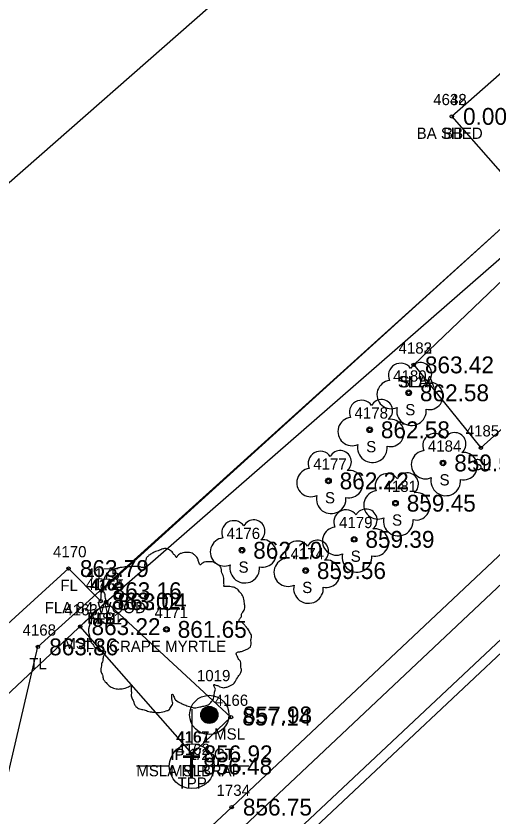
# Model space of a CAD drawing. Extents: x 1622501 to 1626664, y 1117816 to 1121579.
# Drawn here: x 1625061.6 to 1625103.9, y 1120306.8 to 1120378.1 of the extents above; entities that cross this region are included whole.
import ezdxf

# ---------------------------------------------------------------- set-up
doc = ezdxf.new("R2010")
doc.units = 0
for name, color, linetype in [('RD_EX_Bldg', 7, 'Continuous'), ('RD_EX_Bldg_txCode', 7, 'Continuous'), ('RD_EX_Conc', 7, 'Continuous'), ('RD_EX_Conc_txCode', 7, 'Continuous'), ('RD_EX_DR_Pipe', 7, 'Continuous'), ('RD_EX_DV_Prop_txCode', 7, 'Continuous'), ('RD_EX_DV_PropPin', 7, 'Continuous'), ('RD_EX_Fence_Other', 7, 'Continuous'), ('RD_EX_Fence_Other_txCode', 7, 'Continuous'), ('RD_EX_Misc', 7, 'Continuous'), ('RD_EX_Misc_txCode', 7, 'Continuous'), ('RD_EX_Road', 7, 'Continuous'), ('RD_EX_TX_Bldg_ELEV', 7, 'Continuous'), ('RD_EX_TX_Conc_ELEV', 7, 'Continuous'), ('RD_EX_TX_DV_Prop_ELEV', 7, 'Continuous'), ('RD_EX_TX_Fence_Other_ELEV', 7, 'Continuous'), ('RD_EX_TX_Misc_ELEV', 7, 'Continuous'), ('RD_EX_TX_UT_ELEV', 7, 'Continuous'), ('RD_EX_TX_VEG_ELEV', 7, 'Continuous'), ('RD_EX_UT', 7, 'Continuous'), ('RD_EX_UT_txCode', 7, 'Continuous'), ('RD_EX_VEG', 7, 'Continuous'), ('RD_EX_VEG_txCode', 7, 'Continuous'), ('RD_SMD_Locator', 7, 'Continuous')]:
    doc.layers.add(name, color=color, linetype=linetype)

msp = doc.modelspace()

# ---------------------------------------------------------------- linework, layer by layer
at = {"layer": 'RD_EX_Bldg'}
for points in [[(1625050.988, 1120354.576), (1625088.55, 1120387.585), (1625056.123, 1120424.486), (1625018.56, 1120391.478), (1625050.988, 1120354.576)], [(1625100.292, 1120369.177), (1625105.901, 1120362.791), (1625115.068, 1120370.843), (1625109.458, 1120377.229), (1625100.292, 1120369.177)]]:
    msp.add_lwpolyline(points, dxfattribs=at)
at = {"layer": 'RD_EX_Conc'}
for points in [[(1624897.378, 1120127.586), (1624903.697, 1120133.247), (1624939.766, 1120167.411), (1624977.137, 1120202.764), (1625013.589, 1120237.139), (1625049.488, 1120270.838), (1625084.275, 1120303.479), (1625121.787, 1120338.741), (1625157.607, 1120372.541), (1625193.027, 1120405.896), (1625230.27, 1120441.109), (1625263.987, 1120473.049), (1625301.798, 1120509.249), (1625336.15, 1120542.221), (1625372.25, 1120576.993), (1625405.365, 1120609.311), (1625409.32, 1120614.519), (1625412.456, 1120620.32), (1625414.419, 1120627.016), (1625414.966, 1120636.138), (1625412.914, 1120644.37), (1625411.037, 1120648.086), (1625399.274, 1120667.189)], [(1624899.89, 1120137.526), (1624936.243, 1120171.696), (1624973.261, 1120206.726), (1625009.729, 1120241.184), (1625045.817, 1120275.099), (1625080.725, 1120307.719), (1625118.033, 1120342.848), (1625154.459, 1120377.147), (1625189.451, 1120410.103), (1625226.397, 1120445.046), (1625260.082, 1120477.093), (1625298.209, 1120513.612), (1625332.486, 1120546.411), (1625368.395, 1120580.995), (1625401.296, 1120613.087), (1625404.616, 1120617.809), (1625407.287, 1120622.414), (1625408.963, 1120627.094), (1625409.263, 1120635.885), (1625414.414, 1120636.083)]]:
    msp.add_lwpolyline(points, dxfattribs=at)
at = {"layer": 'RD_EX_DR_Pipe'}
msp.add_lwpolyline([(1625495.159, 1120700.169), (1625478.481, 1120693.944), (1625478.481, 1120693.944), (1625401.274, 1120618.609), (1625386.855, 1120595.889), (1625386.855, 1120595.889), (1625239.336, 1120454.576), (1625067.489, 1120292.506), (1624913.323, 1120147.082), (1624906.318, 1120142.577), (1624803.571, 1120043.734), (1624612.212, 1119870.34), (1624528.295, 1119793.118)], dxfattribs=at)
at = {"layer": 'RD_EX_DV_PropPin'}
for p, q in [((1625078.001, 1120315.724), (1625078.001, 1120316.116)), ((1625078.036, 1120315.622), (1625078.036, 1120316.218)), ((1625078.072, 1120315.55), (1625078.072, 1120316.289)), ((1625078.107, 1120315.493), (1625078.107, 1120316.346)), ((1625078.142, 1120315.446), (1625078.142, 1120316.394)), ((1625078.177, 1120315.405), (1625078.177, 1120316.435)), ((1625078.212, 1120315.369), (1625078.212, 1120316.47)), ((1625078.247, 1120315.338), (1625078.247, 1120316.502)), ((1625078.282, 1120315.31), (1625078.282, 1120316.53)), ((1625078.317, 1120315.285), (1625078.317, 1120316.554)), ((1625078.352, 1120315.263), (1625078.352, 1120316.576)), ((1625078.387, 1120315.244), (1625078.387, 1120316.595)), ((1625078.422, 1120315.227), (1625078.422, 1120316.612)), ((1625078.457, 1120315.212), (1625078.457, 1120316.627)), ((1625078.492, 1120315.199), (1625078.492, 1120316.64)), ((1625078.527, 1120315.188), (1625078.527, 1120316.651)), ((1625078.562, 1120315.179), (1625078.562, 1120316.66)), ((1625078.597, 1120315.172), (1625078.597, 1120316.668)), ((1625078.632, 1120315.166), (1625078.632, 1120316.673)), ((1625078.667, 1120315.162), (1625078.667, 1120316.677)), ((1625078.702, 1120315.159), (1625078.702, 1120316.68)), ((1625078.737, 1120315.159), (1625078.737, 1120316.681)), ((1625078.772, 1120315.159), (1625078.772, 1120316.68)), ((1625078.807, 1120315.162), (1625078.807, 1120316.677)), ((1625078.842, 1120315.166), (1625078.842, 1120316.673)), ((1625078.877, 1120315.172), (1625078.877, 1120316.668)), ((1625078.912, 1120315.179), (1625078.912, 1120316.66)), ((1625078.947, 1120315.188), (1625078.947, 1120316.651)), ((1625078.982, 1120315.199), (1625078.982, 1120316.64)), ((1625079.017, 1120315.212), (1625079.017, 1120316.627)), ((1625079.052, 1120315.227), (1625079.052, 1120316.612)), ((1625079.087, 1120315.244), (1625079.087, 1120316.595)), ((1625079.122, 1120315.263), (1625079.122, 1120316.576)), ((1625079.157, 1120315.285), (1625079.157, 1120316.554)), ((1625079.192, 1120315.31), (1625079.192, 1120316.53)), ((1625079.227, 1120315.338), (1625079.227, 1120316.502)), ((1625079.262, 1120315.369), (1625079.262, 1120316.47)), ((1625079.297, 1120315.405), (1625079.297, 1120316.435)), ((1625079.332, 1120315.446), (1625079.332, 1120316.394)), ((1625079.367, 1120315.493), (1625079.367, 1120316.346)), ((1625079.402, 1120315.55), (1625079.402, 1120316.289)), ((1625079.437, 1120315.622), (1625079.437, 1120316.218)), ((1625079.472, 1120315.724), (1625079.472, 1120316.116))]:
    msp.add_line(p, q, dxfattribs=at)
for radius in [1.75, 0.761]:
    msp.add_circle((1625078.737, 1120315.92), radius, dxfattribs=at)
at = {"layer": 'RD_EX_Fence_Other'}
for points in [[(1624882.108, 1120146.413), (1624922.827, 1120188.172), (1624952.576, 1120216.9), (1624993.862, 1120256.562), (1625030.931, 1120289.642), (1625069.578, 1120325.996), (1625106.791, 1120358.455), (1625145.388, 1120394.48), (1625163.872, 1120411.002), (1625180.046, 1120426.703), (1625211.372, 1120456.62), (1625250.442, 1120494.547), (1625284.568, 1120527.631), (1625318.686, 1120557.977), (1625317.764, 1120559.821), (1625354.436, 1120595.487), (1625389.434, 1120629.691)], [(1624968.412, 1120251.923), (1624973.485, 1120246.613), (1625017.999, 1120286.663), (1625019.131, 1120285.989), (1625066.231, 1120328.946), (1625069.089, 1120326.051), (1625069.144, 1120326.972), (1625105.343, 1120359.801), (1625118.176, 1120370.27), (1625118.176, 1120370.27), (1625145.005, 1120394.595), (1625165.443, 1120413.584)]]:
    msp.add_lwpolyline(points, dxfattribs=at)
at = {"layer": 'RD_EX_Misc'}
msp.add_lwpolyline([(1625077.226, 1120312.461), (1625067.266, 1120323.778), (1625069.578, 1120325.996), (1625080.664, 1120315.729), (1625077.226, 1120312.461)], dxfattribs=at)
at = {"layer": 'RD_EX_Road'}
msp.add_lwpolyline([(1624781.367, 1120199.017), (1624784.165, 1120188.994), (1624788.317, 1120183.838), (1624819.769, 1120157.812), (1624850.784, 1120132.057), (1624863.119, 1120123.17), (1624872.562, 1120120.776), (1624881.482, 1120120.158), (1624884.455, 1120120.692), (1624898.026, 1120126.784), (1624903.404, 1120131.449), (1624903.183, 1120131.678), (1624904.185, 1120132.725), (1624940.396, 1120166.874), (1624977.651, 1120202.124), (1625014.07, 1120236.514), (1625050.075, 1120270.322), (1625084.777, 1120302.734), (1625122.295, 1120338.035), (1625158.189, 1120371.975), (1625193.609, 1120405.268), (1625230.886, 1120440.454)], dxfattribs=at)
at = {"layer": 'RD_EX_UT'}
for p, q in [((1625077.183, 1120316.433), (1625077.183, 1120313.363)), ((1625072.252, 1120311.378), (1625075.183, 1120311.378)), ((1625079.183, 1120311.378), (1625082.252, 1120311.378))]:
    msp.add_line(p, q, dxfattribs=at)
msp.add_circle((1625077.183, 1120311.363), 2, dxfattribs=at)
at = {"layer": 'RD_EX_VEG'}
for points in [[(1624992.75, 1120261.436), (1624994.015, 1120256.481), (1625045.588, 1120300.866), (1625059.123, 1120303.266), (1625063.507, 1120321.975), (1625105.343, 1120359.801), (1625167.773, 1120414.629), (1625284.568, 1120527.631), (1625296.639, 1120540.301), (1625291.874, 1120545.154)], [(1625096.903, 1120347.066), (1625102.874, 1120339.698), (1625152.178, 1120384.03), (1625170.927, 1120401.075), (1625165.695, 1120409.022)], [(1625096.903, 1120347.066), (1625107.552, 1120357.235), (1625146.826, 1120391.831), (1625165.695, 1120409.022)]]:
    msp.add_lwpolyline(points, dxfattribs=at)
for centre, radius in [((1625096.462, 1120344.583), 0.25), ((1625092.988, 1120341.291), 0.25), ((1625099.509, 1120338.341), 0.25), ((1625089.325, 1120336.746), 0.25), ((1625095.287, 1120334.761), 0.25), ((1625091.614, 1120331.544), 0.25), ((1625081.644, 1120330.575), 0.25), ((1625087.303, 1120328.766), 0.25), ((1625074.93, 1120323.532), 0.25), ((1625074.918, 1120323.513), 0.0001)]:
    msp.add_circle(centre, radius, dxfattribs=at)
for centre, radius, start, end in [((1625095.741, 1120346.131), 1.084, 34.97629, 204.75602), ((1625097.507, 1120346.285), 0.995, 308.76261, 152.04674), ((1625094.898, 1120344.428), 1.257, 96.45179, 294.73401), ((1625098.301, 1120344.304), 1.218, 256.56668, 98.10463), ((1625092.267, 1120342.838), 1.084, 34.97629, 204.75602), ((1625094.033, 1120342.993), 0.995, 308.76261, 152.04674), ((1625096.707, 1120342.987), 1.318, 166.88266, 5.75893), ((1625091.424, 1120341.135), 1.257, 96.45179, 294.73401), ((1625094.828, 1120341.011), 1.218, 256.56668, 98.10463), ((1625098.788, 1120339.888), 1.084, 34.97629, 204.75602), ((1625100.554, 1120340.043), 0.995, 308.76261, 152.04674), ((1625093.234, 1120339.694), 1.318, 166.88266, 5.75893), ((1625088.604, 1120338.293), 1.084, 34.97629, 204.75602), ((1625090.37, 1120338.448), 0.995, 308.76261, 152.04674), ((1625097.945, 1120338.186), 1.257, 96.45179, 294.73401), ((1625101.349, 1120338.062), 1.218, 256.56668, 98.10463), ((1625087.761, 1120336.59), 1.257, 96.45179, 294.73401), ((1625091.164, 1120336.466), 1.218, 256.56668, 98.10463), ((1625094.566, 1120336.308), 1.084, 34.97629, 204.75602), ((1625096.332, 1120336.463), 0.995, 308.76261, 152.04674), ((1625099.754, 1120336.745), 1.318, 166.88266, 5.75893), ((1625089.57, 1120335.149), 1.318, 166.88266, 5.75893), ((1625093.723, 1120334.605), 1.257, 96.45179, 294.73401), ((1625097.126, 1120334.481), 1.218, 256.56668, 98.10463), ((1625090.893, 1120333.091), 1.084, 34.97629, 204.75602), ((1625092.659, 1120333.246), 0.995, 308.76261, 152.04674), ((1625080.923, 1120332.122), 1.084, 34.97629, 204.75602), ((1625082.689, 1120332.277), 0.995, 308.76261, 152.04674), ((1625095.532, 1120333.164), 1.318, 166.88266, 5.75893), ((1625090.05, 1120331.388), 1.257, 96.45179, 294.73401), ((1625093.454, 1120331.264), 1.218, 256.56668, 98.10463), ((1625080.08, 1120330.419), 1.257, 96.45179, 294.73401), ((1625083.483, 1120330.295), 1.218, 256.56668, 98.10463), ((1625086.582, 1120330.313), 1.084, 34.97629, 204.75602), ((1625088.348, 1120330.468), 0.995, 308.76261, 152.04674), ((1625091.859, 1120329.947), 1.318, 166.88266, 5.75893), ((1625085.739, 1120328.61), 1.257, 96.45179, 294.73401), ((1625089.143, 1120328.486), 1.218, 256.56668, 98.10463), ((1625081.889, 1120328.978), 1.318, 166.88266, 5.75893), ((1625087.549, 1120327.169), 1.318, 166.88266, 5.75893)]:
    msp.add_arc(centre, radius, start, end, dxfattribs=at)
for points in [[(1625075.062, 1120330.699), (1625074.762, 1120330.724), (1625074.438, 1120330.624), (1625074.188, 1120330.524), (1625073.963, 1120330.449), (1625073.738, 1120330.349), (1625073.438, 1120330.174), (1625073.213, 1120329.974), (1625073.088, 1120329.724), (1625073.038, 1120329.499), (1625072.988, 1120329.225), (1625072.988, 1120329.05), (1625072.863, 1120329.025), (1625072.713, 1120329.05), (1625072.463, 1120329.125), (1625072.214, 1120329.125), (1625071.964, 1120329.125), (1625071.614, 1120329.1), (1625071.264, 1120329.1), (1625070.989, 1120329.05), (1625070.664, 1120329), (1625070.289, 1120328.875), (1625069.94, 1120328.75), (1625069.64, 1120328.5), (1625069.39, 1120328.025), (1625069.265, 1120327.675), (1625069.115, 1120327.425), (1625069.265, 1120326.976), (1625069.44, 1120326.626), (1625069.465, 1120326.426), (1625069.54, 1120326.001), (1625069.64, 1120325.776), (1625069.765, 1120325.576), (1625069.69, 1120325.551), (1625069.315, 1120325.501), (1625069.015, 1120325.401), (1625068.59, 1120325.176), (1625068.365, 1120324.951), (1625068.265, 1120324.626), (1625068.24, 1120324.277), (1625068.14, 1120324.077), (1625068.065, 1120323.802), (1625068.04, 1120323.727), (1625067.99, 1120323.402), (1625068.09, 1120322.952), (1625068.115, 1120322.602), (1625068.24, 1120322.377), (1625068.39, 1120322.203), (1625068.565, 1120321.953), (1625068.965, 1120321.728), (1625069.29, 1120321.628), (1625069.49, 1120321.603), (1625069.315, 1120321.103), (1625069.265, 1120320.753), (1625069.14, 1120320.353), (1625069.14, 1120320.278), (1625069.09, 1120319.804), (1625069.24, 1120319.479), (1625069.315, 1120319.104), (1625069.49, 1120318.879), (1625069.765, 1120318.579), (1625070.089, 1120318.354), (1625070.589, 1120318.229), (1625070.989, 1120318.254), (1625071.564, 1120318.429), (1625071.814, 1120318.504), (1625071.789, 1120318.329), (1625071.814, 1120317.954), (1625071.814, 1120317.53), (1625071.964, 1120317.205), (1625072.064, 1120316.93), (1625072.214, 1120316.68), (1625072.538, 1120316.455), (1625072.938, 1120316.38), (1625073.363, 1120316.23), (1625073.813, 1120316.155), (1625074.313, 1120316.13), (1625074.912, 1120316.28), (1625075.187, 1120316.405), (1625075.287, 1120316.58), (1625075.487, 1120316.955), (1625075.437, 1120317.18), (1625075.462, 1120317.78), (1625075.562, 1120317.605), (1625075.737, 1120317.255), (1625076.237, 1120316.955), (1625076.637, 1120316.78), (1625077.111, 1120316.63), (1625077.411, 1120316.555), (1625077.886, 1120316.63), (1625078.261, 1120316.705), (1625078.636, 1120316.83), (1625078.936, 1120317.105), (1625079.111, 1120317.38), (1625079.161, 1120317.655), (1625079.235, 1120318.029), (1625079.285, 1120318.204)], [(1625079.285, 1120318.204), (1625079.211, 1120318.379), (1625079.161, 1120318.629), (1625079.235, 1120318.604), (1625079.41, 1120318.554), (1625079.685, 1120318.429), (1625079.91, 1120318.354), (1625080.235, 1120318.379), (1625080.51, 1120318.479), (1625080.96, 1120318.754), (1625081.235, 1120319.229), (1625081.509, 1120319.629), (1625081.584, 1120319.954), (1625081.534, 1120320.178), (1625081.509, 1120320.678), (1625081.31, 1120320.928), (1625081.26, 1120321.053), (1625081.16, 1120321.453), (1625081.235, 1120321.503), (1625081.509, 1120321.553), (1625081.884, 1120321.678), (1625082.159, 1120321.803), (1625082.384, 1120321.978), (1625082.459, 1120322.203), (1625082.434, 1120322.602), (1625082.484, 1120323.002), (1625082.409, 1120323.152), (1625082.309, 1120323.302), (1625082.234, 1120323.502), (1625082.084, 1120323.652), (1625081.984, 1120323.802), (1625081.884, 1120323.902), (1625081.759, 1120324.052), (1625081.584, 1120324.177), (1625081.435, 1120324.227), (1625081.385, 1120324.377), (1625081.534, 1120324.577), (1625081.584, 1120324.676), (1625081.609, 1120324.901), (1625081.834, 1120325.251), (1625081.884, 1120325.651), (1625081.834, 1120326.076), (1625081.784, 1120326.351), (1625081.634, 1120326.626), (1625081.435, 1120326.876), (1625081.31, 1120327.05), (1625081.135, 1120327.175), (1625080.81, 1120327.3), (1625080.56, 1120327.35), (1625080.21, 1120327.35), (1625080.01, 1120327.4), (1625080.035, 1120327.45), (1625080.035, 1120327.6), (1625080.035, 1120327.875), (1625079.96, 1120328.325), (1625079.81, 1120328.825), (1625079.81, 1120328.85), (1625079.71, 1120329.1), (1625079.485, 1120329.299), (1625079.31, 1120329.399), (1625079.111, 1120329.524), (1625078.861, 1120329.549), (1625078.561, 1120329.549), (1625078.286, 1120329.499), (1625078.086, 1120329.399), (1625077.911, 1120329.274), (1625077.836, 1120329.424), (1625077.736, 1120329.724), (1625077.686, 1120329.874), (1625077.536, 1120330.049), (1625077.311, 1120330.249), (1625076.861, 1120330.374), (1625076.237, 1120330.299), (1625075.937, 1120330.099), (1625075.787, 1120329.924), (1625075.737, 1120330.049), (1625075.537, 1120330.249), (1625075.437, 1120330.424), (1625075.262, 1120330.549), (1625075.112, 1120330.649), (1625075.012, 1120330.699)]]:
    msp.add_spline(points, degree=3, dxfattribs=at)
at = {"layer": 'RD_SMD_Locator'}
for centre in [(1625100.292, 1120369.177), (1625100.292, 1120369.177), (1625096.903, 1120347.066), (1625096.903, 1120347.066), (1625096.462, 1120344.583), (1625092.988, 1120341.291), (1625102.874, 1120339.698), (1625099.509, 1120338.341), (1625089.325, 1120336.746), (1625095.287, 1120334.761), (1625091.614, 1120331.544), (1625081.644, 1120330.575), (1625066.231, 1120328.946), (1625087.303, 1120328.766), (1625069.144, 1120326.972), (1625069.089, 1120326.051), (1625069.578, 1120325.996), (1625069.578, 1120325.996), (1625067.266, 1120323.778), (1625074.93, 1120323.532), (1625063.507, 1120321.975), (1625078.737, 1120315.92), (1625080.664, 1120315.729), (1625077.226, 1120312.461), (1625077.226, 1120312.461), (1625077.183, 1120311.363), (1625080.725, 1120307.719)]:
    msp.add_circle(centre, 0.15, dxfattribs=at)

# ---------------------------------------------------------------- texts
at = {"layer": 'RD_EX_Bldg_txCode'}
for s, p in [('4638', (1625098.638, 1120370.177)), ('4642', (1625098.638, 1120370.177)), ('BA SHED', (1625097.166, 1120367.177)), ('BB', (1625099.512, 1120367.177))]:
    msp.add_text(s, height=1, dxfattribs=at).set_placement(p)
at = {"layer": 'RD_EX_Conc_txCode'}
msp.add_text('1734', height=1, dxfattribs=at).set_placement((1625079.378, 1120308.719))
at = {"layer": 'RD_EX_DV_Prop_txCode'}
for s, p in [('1019', (1625077.634, 1120318.92)), ('IP 1/2 CT', (1625075.28, 1120311.92))]:
    msp.add_text(s, height=1, dxfattribs=at).set_placement(p)
at = {"layer": 'RD_EX_Fence_Other_txCode'}
for s, p in [('4170', (1625064.845, 1120329.946)), ('4175', (1625067.797, 1120327.972)), ('FL', (1625065.499, 1120326.946)), ('4172', (1625067.743, 1120327.051)), ('4165', (1625068.208, 1120326.996)), ('FLA 84 WOOD', (1625064.104, 1120324.972)), ('FLB', (1625067.885, 1120324.051)), ('FL1', (1625068.68, 1120323.996))]:
    msp.add_text(s, height=1, dxfattribs=at).set_placement(p)
at = {"layer": 'RD_EX_Misc_txCode'}
for s, p in [('4164', (1625068.126, 1120326.996)), ('4163', (1625065.849, 1120324.778)), ('MSL', (1625068.075, 1120323.996)), ('MSL', (1625065.763, 1120321.778)), ('4166', (1625079.215, 1120316.729)), ('MSL', (1625079.161, 1120313.729)), ('4167', (1625075.782, 1120313.461)), ('4161', (1625075.839, 1120313.461)), ('MSLA RIP RAP', (1625072.247, 1120310.461)), ('MSLB', (1625075.256, 1120310.461))]:
    msp.add_text(s, height=1, dxfattribs=at).set_placement(p)
at = {"layer": 'RD_EX_TX_Bldg_ELEV'}
msp.add_text('0.00', height=1.5, dxfattribs=at).set_placement((1625101.292, 1120368.427))
msp.add_text('0.00', height=1.5, dxfattribs=at).set_placement((1625101.292, 1120368.427))
at = {"layer": 'RD_EX_TX_Conc_ELEV'}
msp.add_text('856.75', height=1.5, dxfattribs=at).set_placement((1625081.725, 1120306.969))
at = {"layer": 'RD_EX_TX_DV_Prop_ELEV'}
msp.add_text('857.98', height=1.5, dxfattribs=at).set_placement((1625081.737, 1120315.17))
at = {"layer": 'RD_EX_TX_Fence_Other_ELEV'}
for s, p in [('863.79', (1625067.231, 1120328.196)), ('863.16', (1625070.144, 1120326.222)), ('863.02', (1625070.089, 1120325.301)), ('863.04', (1625070.578, 1120325.246))]:
    msp.add_text(s, height=1.5, dxfattribs=at).set_placement(p)
at = {"layer": 'RD_EX_TX_Misc_ELEV'}
for s, p in [('863.04', (1625070.578, 1120325.246)), ('863.22', (1625068.266, 1120323.028)), ('857.14', (1625081.664, 1120314.979)), ('856.92', (1625078.226, 1120311.711)), ('856.92', (1625078.226, 1120311.711))]:
    msp.add_text(s, height=1.5, dxfattribs=at).set_placement(p)
at = {"layer": 'RD_EX_TX_UT_ELEV'}
msp.add_text('856.48', height=1.5, dxfattribs=at).set_placement((1625078.183, 1120310.613))
at = {"layer": 'RD_EX_TX_VEG_ELEV'}
for s, p in [('863.42', (1625097.903, 1120346.316)), ('863.42', (1625097.903, 1120346.316)), ('862.58', (1625097.462, 1120343.833)), ('862.58', (1625093.988, 1120340.541)), ('859.56', (1625100.509, 1120337.591)), ('862.22', (1625090.325, 1120335.996)), ('859.45', (1625096.287, 1120334.011)), ('859.39', (1625092.614, 1120330.794)), ('862.10', (1625082.644, 1120329.825)), ('859.56', (1625088.303, 1120328.016)), ('861.65', (1625075.93, 1120322.782)), ('863.86', (1625064.507, 1120321.225))]:
    msp.add_text(s, height=1.5, dxfattribs=at).set_placement(p)
at = {"layer": 'RD_EX_UT'}
msp.add_text('T', height=2, dxfattribs=at).set_placement((1625076.334, 1120310.316))
at = {"layer": 'RD_EX_UT_txCode'}
for s, p in [('4162', (1625075.813, 1120312.363)), ('TPP', (1625075.915, 1120309.363))]:
    msp.add_text(s, height=1, dxfattribs=at).set_placement(p)
at = {"layer": 'RD_EX_VEG_txCode'}
for s, p in [('4182', (1625095.557, 1120348.066)), ('4183', (1625095.557, 1120348.066)), ('4180', (1625095.076, 1120345.583)), ('SL1A', (1625095.494, 1120345.066)), ('SLA', (1625095.659, 1120345.066)), ('4178', (1625091.642, 1120342.291)), ('S', (1625096.155, 1120342.583)), ('4185', (1625101.528, 1120340.698)), ('S', (1625092.681, 1120339.291)), ('4184', (1625098.162, 1120339.341)), ('4177', (1625087.978, 1120337.746)), ('SL', (1625102.118, 1120337.698)), ('4181', (1625094.224, 1120335.761)), ('S', (1625099.202, 1120336.341)), ('S', (1625089.018, 1120334.746)), ('4179', (1625090.267, 1120332.544)), ('S', (1625094.98, 1120332.761)), ('4176', (1625080.274, 1120331.575)), ('4174', (1625085.957, 1120329.766)), ('S', (1625091.307, 1120329.544)), ('S', (1625081.337, 1120328.575)), ('S', (1625086.996, 1120326.766)), ('4171', (1625073.867, 1120324.532)), ('4168', (1625062.137, 1120322.975)), ('T 8 CRAPE MYRTLE', (1625067.525, 1120321.532)), ('TL', (1625062.736, 1120319.975))]:
    msp.add_text(s, height=1, dxfattribs=at).set_placement(p)

doc.saveas('drawing.dxf')
